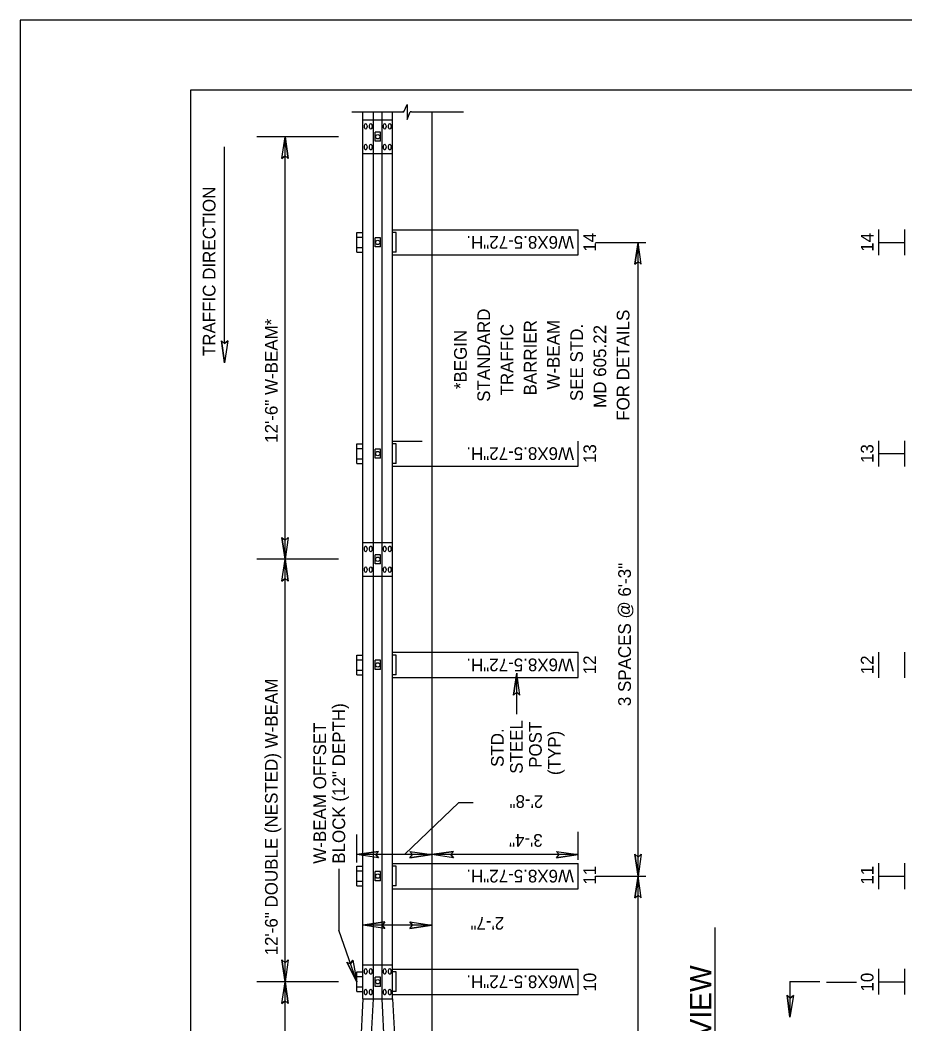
# Model space of a CAD drawing. Extents: x 12.2 to 54.5, y -7.8 to 16.1.
# Drawn here: x 46.034 to 50.224, y -1.531 to 3.22 of the extents above; entities that cross this region are included whole.
import ezdxf

# ---------------------------------------------------------------- set-up
doc = ezdxf.new("R2010")
doc.units = 0
for name, color, linetype in [('BORD-LINE', 7, 'Continuous'), ('DETL-DIMS', 7, 'Continuous'), ('DETL-LINE', 7, 'Continuous'), ('DETL-NOTE', 7, 'Continuous'), ('DETL-TITL', 7, 'Continuous'), ('USER-BORD', 7, 'Continuous')]:
    doc.layers.add(name, color=color, linetype=linetype)

msp = doc.modelspace()

# ---------------------------------------------------------------- linework, layer by layer
at = {"layer": 'BORD-LINE'}
msp.add_lwpolyline([(46.8431, 2.8902), (54.2173, 2.8902), (54.2173, -7.4629), (46.8431, -7.4629)], close=True, dxfattribs=at)
at = {"layer": 'DETL-DIMS'}
for p, q in [((47.5412, 2.668), (47.1551, 2.668)), ((47.274, 2.5647), (47.289, 2.668)), ((47.289, -1.332), (47.289, 2.668)), ((47.3041, 2.5647), (47.289, 2.668)), ((47.0023, 1.6886), (47.0023, 2.6199)), ((47.274, 2.5647), (47.289, 2.5776)), ((47.3041, 2.5647), (47.289, 2.5776)), ((48.7582, 2.168), (48.9965, 2.168)), ((48.945, 2.0646), (48.96, 2.168)), ((48.96, -0.832), (48.96, 2.168)), ((48.9751, 2.0646), (48.96, 2.168)), ((50.1004, 2.168), (50.1004, 2.168)), ((50.1004, 2.168), (50.1004, 2.168)), ((50.1004, 2.168), (50.1004, 2.168)), ((50.1004, 2.168), (50.1004, 2.168)), ((50.1004, 2.168), (50.1004, 2.168)), ((50.1004, 2.168), (50.1004, 2.168)), ((48.945, 2.0646), (48.96, 2.0776)), ((48.9751, 2.0646), (48.96, 2.0776)), ((46.9872, 1.7015), (47.0023, 1.5982)), ((46.9872, 1.7015), (47.0023, 1.6886)), ((47.0174, 1.7015), (47.0023, 1.5982)), ((47.0174, 1.7015), (47.0023, 1.6886)), ((50.1004, 1.168), (50.1004, 1.168)), ((50.1004, 1.168), (50.1004, 1.168)), ((50.1004, 1.168), (50.1004, 1.168)), ((50.1004, 1.168), (50.1004, 1.168)), ((47.2739, 0.7713), (47.289, 0.668)), ((47.2739, 0.7713), (47.289, 0.7584)), ((47.304, 0.7713), (47.289, 0.668)), ((47.304, 0.7713), (47.289, 0.7584)), ((47.5412, 0.668), (47.1551, 0.668)), ((47.5412, 0.668), (47.1551, 0.668)), ((47.5412, 0.668), (47.1761, 0.668)), ((47.274, 0.5647), (47.289, 0.668)), ((47.3041, 0.5647), (47.289, 0.668)), ((47.274, 0.5647), (47.289, 0.5776)), ((47.3041, 0.5647), (47.289, 0.5776)), ((50.1004, 0.168), (50.1004, 0.168)), ((50.1004, 0.168), (50.1004, 0.168)), ((50.1004, 0.168), (50.1004, 0.168)), ((50.1004, 0.168), (50.1004, 0.168)), ((50.1004, 0.168), (50.1004, 0.168)), ((50.1004, 0.168), (50.1004, 0.168)), ((48.3706, 0.0254), (48.3857, 0.1287)), ((48.3857, -0.0646), (48.3857, 0.1287)), ((48.4007, 0.0254), (48.3857, 0.1287)), ((48.3706, 0.0254), (48.3857, 0.0383)), ((48.4007, 0.0254), (48.3857, 0.0383)), ((47.8539, -0.7297), (48.1117, -0.4826)), ((48.1117, -0.4826), (48.179, -0.4826)), ((47.6287, -0.7672), (47.6287, -0.6353)), ((48.6773, -0.7542), (48.6773, -0.6223)), ((47.732, -0.7147), (47.6287, -0.7297)), ((47.732, -0.7448), (47.6287, -0.7297)), ((47.9832, -0.7297), (47.6287, -0.7297)), ((47.732, -0.7147), (47.719, -0.7297)), ((47.732, -0.7448), (47.719, -0.7297)), ((47.88, -0.7146), (47.9832, -0.7297)), ((47.88, -0.7146), (47.8929, -0.7297)), ((47.8801, -0.7447), (47.9832, -0.7297)), ((47.8801, -0.7447), (47.8929, -0.7297)), ((48.0865, -0.7147), (47.9832, -0.7297)), ((48.6773, -0.7297), (47.9832, -0.7297)), ((48.0865, -0.7448), (47.9832, -0.7297)), ((48.0865, -0.7147), (48.0735, -0.7297)), ((48.0865, -0.7448), (48.0735, -0.7297)), ((48.574, -0.7146), (48.6773, -0.7297)), ((48.574, -0.7146), (48.5869, -0.7297)), ((48.5741, -0.7447), (48.6773, -0.7297)), ((48.5741, -0.7447), (48.5869, -0.7297)), ((48.945, -0.7286), (48.96, -0.832)), ((48.945, -0.7286), (48.96, -0.7416)), ((48.9751, -0.7286), (48.96, -0.832)), ((48.9751, -0.7286), (48.96, -0.7416)), ((47.5441, -0.7968), (47.5441, -1.0871)), ((48.7582, -0.832), (48.9965, -0.832)), ((48.945, -0.9354), (48.96, -0.832)), ((48.96, -2.832), (48.96, -0.832)), ((48.9751, -0.9354), (48.96, -0.832)), ((50.1004, -0.832), (50.1004, -0.832)), ((50.1004, -0.832), (50.1004, -0.832)), ((50.1004, -0.832), (50.1004, -0.832)), ((50.1004, -0.832), (50.1004, -0.832)), ((48.945, -0.9354), (48.96, -0.9224)), ((48.9751, -0.9354), (48.96, -0.9224)), ((47.6287, -1.332), (47.5441, -1.0871)), ((47.7612, -1.049), (47.6579, -1.064)), ((47.7612, -1.0791), (47.6579, -1.064)), ((47.9832, -1.064), (47.6579, -1.064)), ((47.7612, -1.049), (47.7482, -1.064)), ((47.7612, -1.0791), (47.7482, -1.064)), ((47.88, -1.049), (47.9832, -1.064)), ((47.88, -1.049), (47.8929, -1.064)), ((47.8801, -1.0791), (47.9832, -1.064)), ((47.8801, -1.0791), (47.8929, -1.064)), ((47.2739, -1.2287), (47.289, -1.332)), ((47.2739, -1.2287), (47.289, -1.2416)), ((47.304, -1.2287), (47.289, -1.332)), ((47.304, -1.2287), (47.289, -1.2416)), ((47.6092, -1.2293), (47.5992, -1.2465)), ((47.6092, -1.2293), (47.6287, -1.332)), ((47.5808, -1.2391), (47.6287, -1.332)), ((47.5808, -1.2391), (47.5992, -1.2465)), ((49.6796, -1.33), (49.6796, -1.4993)), ((49.6796, -1.33), (49.8212, -1.33)), ((47.5412, -1.332), (47.1551, -1.332)), ((47.274, -1.4353), (47.289, -1.332)), ((47.3041, -1.4353), (47.289, -1.332)), ((47.289, -5.5129), (47.289, -1.332)), ((49.853, -1.3335), (49.9937, -1.3335)), ((50.1004, -1.332), (50.1004, -1.332)), ((50.1004, -1.332), (50.1004, -1.332)), ((50.1004, -1.332), (50.1004, -1.332)), ((50.1004, -1.332), (50.1004, -1.332)), ((47.274, -1.4353), (47.289, -1.4224)), ((47.3041, -1.4353), (47.289, -1.4224)), ((47.6579, -1.412), (47.6129, -2.252)), ((47.6629, -2.252), (47.7079, -1.412)), ((47.7929, -2.252), (47.7479, -1.412)), ((47.7979, -1.412), (47.8429, -2.252)), ((49.6661, -1.3957), (49.6796, -1.4993)), ((49.6661, -1.3957), (49.681, -1.4088)), ((49.6963, -1.3962), (49.6796, -1.4993)), ((49.6963, -1.3962), (49.681, -1.4088))]:
    msp.add_line(p, q, dxfattribs=at)
for points in [[(47.274, 2.5647), (47.289, 2.668), (47.3041, 2.5647), (47.289, 2.5776)], [(48.9751, 2.0646), (48.96, 2.168), (48.945, 2.0646), (48.96, 2.0776)], [(47.0174, 1.7015), (47.0023, 1.5982), (46.9872, 1.7015), (47.0023, 1.6886)], [(47.304, 0.7713), (47.289, 0.668), (47.2739, 0.7713), (47.289, 0.7584)], [(47.274, 0.5647), (47.289, 0.668), (47.3041, 0.5647), (47.289, 0.5776)], [(48.4007, 0.0254), (48.3857, 0.1287), (48.3706, 0.0254), (48.3857, 0.0383)], [(47.732, -0.7448), (47.6287, -0.7297), (47.732, -0.7147), (47.719, -0.7297)], [(47.88, -0.7146), (47.9832, -0.7297), (47.8801, -0.7447), (47.8929, -0.7297)], [(48.0865, -0.7448), (47.9832, -0.7297), (48.0865, -0.7147), (48.0735, -0.7297)], [(48.574, -0.7146), (48.6773, -0.7297), (48.5741, -0.7447), (48.5869, -0.7297)], [(48.9751, -0.7286), (48.96, -0.832), (48.945, -0.7286), (48.96, -0.7416)], [(48.9751, -0.9354), (48.96, -0.832), (48.945, -0.9354), (48.96, -0.9224)], [(47.7612, -1.0791), (47.6579, -1.064), (47.7612, -1.049), (47.7482, -1.064)], [(47.88, -1.049), (47.9832, -1.064), (47.8801, -1.0791), (47.8929, -1.064)], [(47.304, -1.2287), (47.289, -1.332), (47.2739, -1.2287), (47.289, -1.2416)], [(47.6092, -1.2293), (47.6287, -1.332), (47.5808, -1.2391), (47.5992, -1.2465)], [(47.274, -1.4353), (47.289, -1.332), (47.3041, -1.4353), (47.289, -1.4224)], [(49.6963, -1.3962), (49.6796, -1.4993), (49.6661, -1.3957), (49.681, -1.4088)]]:
    msp.add_lwpolyline(points, close=True, dxfattribs=at)
at = {"layer": 'DETL-LINE'}
for p, q in [((47.8519, 2.7851), (47.8664, 2.821)), ((47.8664, 2.821), (47.8664, 2.7492)), ((47.6056, 2.7851), (47.8519, 2.7851)), ((47.6579, -1.412), (47.6579, 2.7851)), ((47.7079, -1.412), (47.7079, 2.7851)), ((47.7479, -1.412), (47.7479, 2.7851)), ((47.7979, -1.412), (47.7979, 2.7851)), ((47.8519, 2.7851), (47.8458, 2.7851)), ((47.8664, 2.7492), (47.8808, 2.7851)), ((47.887, 2.7851), (47.8808, 2.7851)), ((47.887, 2.7851), (48.1332, 2.7851)), ((47.9832, 2.7851), (47.9832, -5.332)), ((47.6579, 2.748), (47.7979, 2.748)), ((47.7407, 2.6897), (47.7151, 2.6897)), ((47.7151, 2.6464), (47.7151, 2.6897)), ((47.7407, 2.6464), (47.7407, 2.6897)), ((47.7407, 2.6464), (47.7151, 2.6464)), ((47.6579, 2.588), (47.7979, 2.588)), ((47.6287, 2.2147), (47.6579, 2.2147)), ((47.6287, 2.1214), (47.6287, 2.2147)), ((47.6287, 2.1926), (47.6579, 2.1926)), ((47.7407, 2.1897), (47.7151, 2.1897)), ((47.7151, 2.1464), (47.7151, 2.1897)), ((47.7407, 2.1464), (47.7407, 2.1897)), ((47.7979, 2.2277), (47.9382, 2.2277)), ((47.8146, 2.2147), (47.7979, 2.2147)), ((47.8146, 2.1214), (47.8146, 2.2147)), ((47.9382, 2.2277), (48.6773, 2.2277)), ((48.6773, 2.1084), (48.6773, 2.2277)), ((50.1004, 2.1071), (50.1004, 2.229)), ((50.223, 2.1071), (50.223, 2.229)), ((47.6287, 2.1435), (47.6579, 2.1435)), ((47.7407, 2.1464), (47.7151, 2.1464)), ((50.1004, 2.168), (50.223, 2.168)), ((47.6287, 2.1214), (47.6579, 2.1214)), ((47.8146, 2.1214), (47.7979, 2.1214)), ((47.7979, 2.1084), (47.9382, 2.1084)), ((47.9382, 2.1084), (48.6773, 2.1084)), ((47.6287, 1.2147), (47.6579, 1.2147)), ((47.6287, 1.1214), (47.6287, 1.2147)), ((47.6287, 1.1926), (47.6579, 1.1926)), ((47.7407, 1.1897), (47.7151, 1.1897)), ((47.7151, 1.1464), (47.7151, 1.1897)), ((47.7407, 1.1464), (47.7407, 1.1897)), ((47.7979, 1.2277), (47.9382, 1.2277)), ((47.8146, 1.2147), (47.7979, 1.2147)), ((47.8146, 1.1214), (47.8146, 1.2147)), ((48.6773, 1.1084), (48.6773, 1.2277)), ((50.1004, 1.1071), (50.1004, 1.229)), ((50.223, 1.1071), (50.223, 1.229)), ((47.6287, 1.1435), (47.6579, 1.1435)), ((47.7407, 1.1464), (47.7151, 1.1464)), ((50.1004, 1.168), (50.223, 1.168)), ((47.6287, 1.1214), (47.6579, 1.1214)), ((47.8146, 1.1214), (47.7979, 1.1214)), ((47.7979, 1.1084), (47.9382, 1.1084)), ((47.9382, 1.1084), (48.6773, 1.1084)), ((47.6579, 0.748), (47.7979, 0.748)), ((47.7407, 0.6897), (47.7151, 0.6897)), ((47.7151, 0.6464), (47.7151, 0.6897)), ((47.7407, 0.6464), (47.7407, 0.6897)), ((47.7407, 0.6464), (47.7151, 0.6464)), ((47.6579, 0.588), (47.7979, 0.588)), ((47.6287, 0.2147), (47.6579, 0.2147)), ((47.6287, 0.1214), (47.6287, 0.2147)), ((47.6287, 0.1926), (47.6579, 0.1926)), ((47.7979, 0.2277), (47.9382, 0.2277)), ((47.8146, 0.2147), (47.7979, 0.2147)), ((47.8146, 0.1214), (47.8146, 0.2147)), ((47.9382, 0.2277), (48.6773, 0.2277)), ((48.6773, 0.1084), (48.6773, 0.2277)), ((50.1004, 0.1071), (50.1004, 0.229)), ((50.223, 0.1071), (50.223, 0.229)), ((47.6287, 0.1435), (47.6579, 0.1435)), ((47.7407, 0.1897), (47.7151, 0.1897)), ((47.7151, 0.1464), (47.7151, 0.1897)), ((47.7407, 0.1464), (47.7151, 0.1464)), ((47.7407, 0.1464), (47.7407, 0.1897)), ((47.6287, 0.1214), (47.6579, 0.1214)), ((47.8146, 0.1214), (47.7979, 0.1214)), ((47.7979, 0.1084), (47.9382, 0.1084)), ((47.9382, 0.1084), (48.6773, 0.1084)), ((47.6287, -0.7853), (47.6579, -0.7853)), ((47.6287, -0.8786), (47.6287, -0.7853)), ((47.6287, -0.8074), (47.6579, -0.8074)), ((47.7979, -0.7723), (47.9382, -0.7723)), ((47.8146, -0.7853), (47.7979, -0.7853)), ((47.8146, -0.8786), (47.8146, -0.7853)), ((47.9382, -0.7723), (48.6773, -0.7723)), ((48.6773, -0.8916), (48.6773, -0.7723)), ((50.1004, -0.8929), (50.1004, -0.771)), ((50.223, -0.8929), (50.223, -0.771)), ((47.7407, -0.8103), (47.7151, -0.8103)), ((47.7151, -0.8536), (47.7151, -0.8103)), ((47.7407, -0.8536), (47.7151, -0.8536)), ((47.7407, -0.8536), (47.7407, -0.8103)), ((50.1004, -0.832), (50.223, -0.832)), ((47.6287, -0.8565), (47.6579, -0.8565)), ((47.6287, -0.8786), (47.6579, -0.8786)), ((47.8146, -0.8786), (47.7979, -0.8786)), ((47.7979, -0.8916), (47.9382, -0.8916)), ((47.9382, -0.8916), (48.6773, -0.8916)), ((47.6579, -1.252), (47.7979, -1.252)), ((47.7979, -1.2723), (47.9382, -1.2723)), ((47.9382, -1.2723), (48.6773, -1.2723)), ((48.6773, -1.3916), (48.6773, -1.2723)), ((50.1004, -1.3929), (50.1004, -1.271)), ((50.223, -1.3929), (50.223, -1.271)), ((47.6287, -1.2853), (47.6579, -1.2853)), ((47.6287, -1.3786), (47.6287, -1.2853)), ((47.6287, -1.3074), (47.6579, -1.3074)), ((47.7407, -1.3103), (47.7151, -1.3103)), ((47.7151, -1.3536), (47.7151, -1.3103)), ((47.7407, -1.3536), (47.7407, -1.3103)), ((47.8146, -1.2853), (47.7979, -1.2853)), ((47.8146, -1.3786), (47.8146, -1.2853)), ((47.6287, -1.3565), (47.6579, -1.3565)), ((47.7407, -1.3536), (47.7151, -1.3536)), ((50.1004, -1.332), (50.223, -1.332)), ((47.6287, -1.3786), (47.6579, -1.3786)), ((47.6579, -1.412), (47.7979, -1.412)), ((47.8146, -1.3786), (47.7979, -1.3786)), ((47.7979, -1.3916), (47.9382, -1.3916)), ((47.9382, -1.3916), (48.6773, -1.3916))]:
    msp.add_line(p, q, dxfattribs=at)
for centre in [(47.7279, 2.668), (47.7279, 2.168), (47.7279, 1.168), (47.7279, 0.668), (47.7279, 0.168), (47.7279, -0.832), (47.7279, -1.332)]:
    msp.add_circle(centre, 0.0102, dxfattribs=at)
for centre in [(47.6709, 2.717), (47.6949, 2.717), (47.7609, 2.717), (47.7849, 2.717), (47.6709, 2.619), (47.6949, 2.619), (47.7609, 2.619), (47.7849, 2.619), (47.6709, 0.717), (47.6949, 0.717), (47.7609, 0.717), (47.7849, 0.717), (47.6709, 0.619), (47.6949, 0.619), (47.7609, 0.619), (47.7849, 0.619), (47.6709, -1.283), (47.6949, -1.283), (47.7609, -1.283), (47.7849, -1.283), (47.6709, -1.381), (47.6949, -1.381), (47.7609, -1.381), (47.7849, -1.381)]:
    msp.add_ellipse(centre, major_axis=(0, 0.0133), ratio=0.45311, dxfattribs=at)
at = {"layer": 'DETL-TITL'}
msp.add_line((49.3252, -2.38), (49.3252, -1.0753), dxfattribs=at)
at = {"layer": 'USER-BORD'}
msp.add_lwpolyline([(54.5342, 3.2202), (46.0342, 3.2202), (46.0342, -7.7798), (54.5342, -7.7798)], close=True, dxfattribs=at)

# ---------------------------------------------------------------- texts
at = {"layer": 'DETL-NOTE'}
for s, rotation, p in [('TRAFFIC DIRECTION', 90, (46.9594, 1.6295)), ('W6X8.5-72"H. ', 180, (48.6571, 2.198)), ('14', 90, (48.7618, 2.1234)), ('14', 90, (50.075, 2.1234)), ('STANDARD', 90, (48.2594, 1.4132)), ('FOR DETAILS', 90, (48.9194, 1.3234)), ('12\'-6" W-BEAM*', 90, (47.2539, 1.219)), ('TRAFFIC', 90, (48.3694, 1.4433)), ('BARRIER', 90, (48.4794, 1.4433)), ('W-BEAM', 90, (48.5894, 1.4712)), ('SEE STD.', 90, (48.6994, 1.4167)), ('MD 605.22', 90, (48.8094, 1.3845)), ('*BEGIN', 90, (48.1494, 1.4733)), ('W6X8.5-72"H. ', 180, (48.6571, 1.198)), ('13', 90, (48.7618, 1.1234)), ('13', 90, (50.075, 1.1234)), ('3 SPACES @ 6\'-3"', 90, (48.9263, -0.0273)), ('W6X8.5-72"H. ', 180, (48.6571, 0.198)), ('12', 90, (48.7618, 0.1234)), ('12', 90, (50.075, 0.1234)), ('12\'-6" DOUBLE (NESTED) W-BEAM', 90, (47.2539, -1.2072)), ('BLOCK (12" DEPTH)', 90, (47.5734, -0.7733)), ('W-BEAM OFFSET ', 90, (47.4834, -0.7733)), ('STD.', 90, (48.3241, -0.3151)), ('STEEL', 90, (48.4141, -0.3473)), ('POST', 90, (48.5041, -0.3194)), ('(TYP)', 90, (48.5941, -0.3536)), ('2\'-8"', 180, (48.5112, -0.449)), ('3\'-4"', 180, (48.509, -0.6328)), ('W6X8.5-72"H. ', 180, (48.6571, -0.802)), ('11', 90, (48.7618, -0.8725)), ('11', 90, (50.075, -0.8724)), ('2\'-7"', 180, (48.3264, -1.0252)), ('W6X8.5-72"H. ', 180, (48.6571, -1.302)), ('10', 90, (48.7618, -1.3785)), ('10', 90, (50.075, -1.3785))]:
    msp.add_text(s, height=0.06, rotation=rotation, dxfattribs=at).set_placement(p)
at = {"layer": 'DETL-TITL'}
msp.add_text('ELEVATION VIEW', height=0.1, rotation=90, dxfattribs=at).set_placement((49.3066, -2.3836))

doc.saveas('drawing.dxf')
